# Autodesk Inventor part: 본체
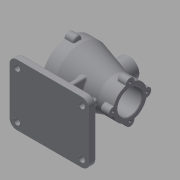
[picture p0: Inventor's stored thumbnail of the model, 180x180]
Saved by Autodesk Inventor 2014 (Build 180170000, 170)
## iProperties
Created: 2020-12
Part Number: 본체
Material: Generic
Document SubType Name: Modeling
Designer: kh
Density: 1 g/cm^3
Appearance: Default
Author: kh
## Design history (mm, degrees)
sketch "Sketch1"
  geometry: L1 (-65, -50)-(65, -50); L2 (65, -50)-(65, 50); L3 (65, 50)-(-65, 50); L4 (-65, 50)-(-65, -50); L5 (-65, -50)-(65, 50); L6 (65, -50)-(-65, 50); 1 further point
  constraints: 12 end point, 2 midpoint, 2 parallel, 1 horizontal, 1 perpendicular
  dimensions: "d0" = 130 distance of L2.end L3.end; "d1" = 100 distance of L1.end L2.end
extrude "Extrusion1" new body sketch "Sketch1" distance "d2" = 12; taper "d3" = 0 deg
sketch "Sketch2"
  geometry: L1 (-70.278, 82)-(64.917, 82); L2 (65, 0)-(-65, 0) reference; L3 (-50, 82)-(-50, 126); L4 (-50, 126)-(-30, 126); L5 (-30, 126)-(25, 109.5); L6 (25, 109.5)-(50, 109.5); L7 (50, 109.5)-(50, 82); L8 (-50, 82)-(50, 82); 1 further point
  constraints: 14 end point, 3 perpendicular, 2 point on line, 1 collinear, 1 horizontal, 1 parallel
  dimensions: "d4" = 82 distance between parallel lines of L2 L1; "d5" = 88 diameter of L4 L1; "d6" = 55 diameter of L6 L1; "d7" = 100 distance between parallel lines of L7 L3; "d8" = 50 distance from line of L3 point (0, 0); "d9" = 20 distance of L3.end L4.end; "d113" = 25 distance from line of L5.end L7
revolve "Revolution1" sketch "Sketch2" stored, may be unused: angle "d11" = 90 deg
sketch "Sketch3"
  geometry: L1 (-24, -4)-(24, -4); L2 (24, -4)-(24, 4); L3 (24, 4)-(-24, 4); L4 (-24, 4)-(-24, -4); L5 (-24, -4)-(24, 4); L6 (24, -4)-(-24, 4); 1 further point
  constraints: 12 end point, 2 midpoint, 2 parallel, 1 horizontal, 1 perpendicular
  dimensions: "d12" = 8 distance of L1.end L2.end; "d13" = 48 distance of L2.end L3.end
extrude "Extrusion2" join sketch "Sketch3" distance "d14" = 70.25; taper "d15" = 0 deg
sketch "Sketch4"
  geometry: L1 (9.974, 25)-(50.933, 25); L2 (12, -50)-(12, 50) reference; 1 further point
  constraints: 2 end point, 1 perpendicular
  dimensions: "d16" = 25 distance from line of point (0, 0) L1
feature "Rib1" sketch "Sketch4" dims "d17" = 1, "d18" = 8, "d19" = 0, "d20" = 0, "d21" = 1, "d22" = 1
sketch "Sketch5"
  geometry: L1 (8.739, -25)-(54.792, -25); 1 further point
  constraints: 2 end point, 1 horizontal
  dimensions: "d23" = 25 distance from line of L1 point (0, 0)
feature "Rib2" sketch "Sketch5" dims "d24" = 1, "d25" = 8, "d26" = 0, "d27" = 0, "d28" = 1, "d29" = 1
sketch "Sketch6"
  geometry: C1 r 7 at (0, 44); 3 further points
  constraints: 3 vertical alignment, 1 centre point, 2 other
  dimensions: "d30" = 14 diameter of C1
extrude "Extrusion3" join sketch "Sketch6" distance "d31" = 15; taper "d32" = 0 deg
pattern_circular "Circular Pattern1" dims angle "d34" = 360 deg
sketch "Sketch7"
  geometry: C1 r 7 at (0, 27.5); 2 further points
  constraints: 2 vertical alignment, 1 centre point, 1 other
  dimensions: "d36" = 14 diameter of C1
extrude "Extrusion4" join sketch "Sketch7" distance "d37" = 15; taper "d38" = 0 deg
pattern_circular "Circular Pattern2" dims angle "d40" = 360 deg
workplane "Work Plane1"
sketch "Sketch8"
  geometry: C1 r 17 at (0, 0); 1 further point
  constraints: 1 centre point, 1 coincident
  dimensions: "d43" = 34 diameter of C1
extrude "Extrusion5" join sketch "Sketch8" distance "d44" = 45; taper "d45" = 0 deg
sketch "Sketch10"
  geometry: C1 r 32 at (0, -44); A1 r 44 centre (0, -44) between (-6.978, -0.557) and (-43.443, -37.022) reference; 1 further point
  constraints: 1 centre point, 1 coincident
  dimensions: "d46" = 64 diameter of C1
extrude "Extrusion6" cut sketch "Sketch10" distance "d47" = 23; taper "d48" = 0 deg
sketch "Sketch11"
  geometry: C1 r 32 at (0, 0) reference; C2 r 26 at (0, 0); 1 further point
  constraints: 1 centre point, 1 coincident
  dimensions: "d49" = 52 diameter of C2
extrude "Extrusion7" cut sketch "Sketch11" distance "d50" = 47; taper "d51" = 0 deg
sketch "Sketch12"
  geometry: C1 r 26 at (0, 0) reference; C2 r 20 at (0, 0); 1 further point
  constraints: 1 centre point, 1 coincident
  dimensions: "d52" = 40 diameter of C2
extrude "Extrusion8" cut sketch "Sketch12" distance "d53" = 30; taper "d54" = 0 deg
hole "Hole1" diameter "d57" = 22; stored, may be unused: countersink angle "d61" = 90 deg, drill point angle "d63" = 0 deg; dims "d55" = 10, "d56" = 10, "d58" = 6, "d59" = 28, "d60" = 1, "d62" = 45
hole "Hole2" diameter "d66" = 4.134; stored, may be unused: countersink angle "d70" = 90 deg, drill point angle "d72" = 118 deg; dims "d64" = 10, "d65" = 10, "d67" = 9, "d68" = 28, "d69" = 1, "d71" = 11
pattern_circular "Circular Pattern3" dims angle "d74" = 360 deg
hole "Hole3" diameter "d78" = 4.134; stored, may be unused: countersink angle "d82" = 90 deg, drill point angle "d84" = 118 deg; dims "d76" = 10, "d77" = 10, "d79" = 9, "d80" = 28, "d81" = 1, "d83" = 11
pattern_circular "Circular Pattern4" dims angle "d86" = 360 deg
fillet "Fillet1" dims "d88" = 12
hole "Hole4" diameter "d91" = 10; stored, may be unused: countersink angle "d95" = 90 deg, drill point angle "d97" = 0 deg; dims "d92" = 10, "d93" = 28, "d94" = 1, "d96" = 11, "d98" = 10, "d99" = 10
pattern_linear "Rectangular Pattern1"
sketch "Sketch13"
  geometry: L1 (-65, 38)-(-65, -38) reference; L2 (-53, -50)-(53, -50) reference; 2 further points
  constraints: 1 other
  dimensions: "d104" = 65 distance from line of L1 point (0, -40); "d105" = 10 distance from line of L2 point (0, -40)
emboss "Emboss1" sketch "Sketch13" dims "d0" = 130, "d1" = 100, "d106" = 0.5, "d107" = 0
chamfer "Chamfer1" distance "d108" = 1; stored, may be unused: second distance "d109" = 2, angle "d110" = 45 deg
fillet "Fillet2" dims "d111" = 3
fillet "Fillet3" dims "d112" = 1
fillet "Fillet4" dims "d114" = 3
body "Solid1"
other parameters: "d42" = -85
